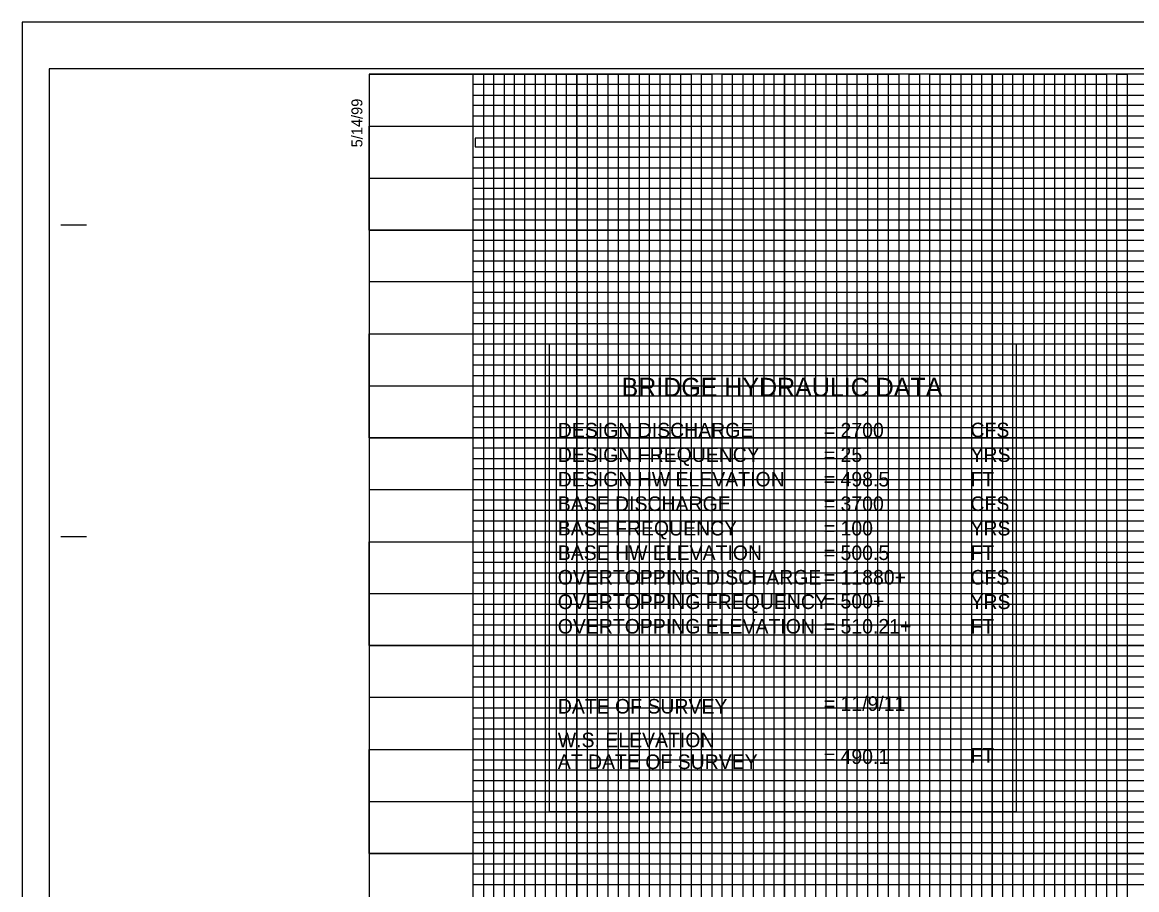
# Model space of a CAD drawing. Extents: x 573715 to 575626, y -55474 to -54374.
# Drawn here: x 573715 to 574252, y -54792 to -54374 of the extents above; entities that cross this region are included whole.
import ezdxf

# ---------------------------------------------------------------- set-up
doc = ezdxf.new("R2010")
doc.units = 0
for name, color, linetype in [('Default', 7, 'Continuous'), ('Prop Grid Mask', 7, 'Continuous'), ('Sheet Cutting Line CELL', 7, 'Continuous'), ('Sheet DOT Grid CELL', 7, 'Continuous'), ('Sheet Layout Profile Border', 7, 'Continuous'), ('Sheet Plot Border Inside CELL', 7, 'Continuous'), ('Sheet Plot Border Outside CELL', 7, 'Continuous'), ('Sheet Profile CELL', 7, 'Continuous'), ('Sheet Profile Grid Major CELL', 7, 'Continuous'), ('Sheet Profile Grid Middle CELL', 7, 'Continuous'), ('Sheet Profile Grid Minor CELL', 7, 'Continuous')]:
    doc.layers.add(name, color=color, linetype=linetype)

msp = doc.modelspace()

# ---------------------------------------------------------------- linework, layer by layer
at = {"layer": 'Prop Grid Mask'}
msp.add_lwpolyline([(573968.92, -54754.28), (574193.92, -54754.28), (574193.92, -54529.28), (573968.92, -54529.28)], close=True, dxfattribs=at)
at = {"layer": 'Sheet Cutting Line CELL'}
for p, q in [((573715.27, -54374.42), (573715.27, -55474.42)), ((575399.27, -54374.42), (573715.27, -54374.42)), ((573715.27, -54374.42), (573715.27, -55474.42))]:
    msp.add_line(p, q, dxfattribs=at)
at = {"layer": 'Sheet DOT Grid CELL'}
for p, q in [((573932.27, -54399.42), (573932.27, -55424.42)), ((573982.27, -54399.42), (573982.27, -55424.42)), ((574032.27, -54399.42), (574032.27, -55424.42)), ((574082.27, -54399.42), (574082.27, -55424.42)), ((574132.27, -54399.42), (574132.27, -55424.42)), ((574182.27, -54399.42), (574182.27, -55424.42)), ((574232.27, -54399.42), (574232.27, -55424.42)), ((573882.27, -54424.42), (575182.22, -54424.42)), ((573882.27, -54474.42), (575182.22, -54474.42)), ((573882.27, -54524.42), (575182.22, -54524.42)), ((573882.27, -54574.42), (575382.27, -54574.42)), ((573882.27, -54624.42), (575382.27, -54624.42)), ((573882.27, -54674.42), (575382.27, -54674.42)), ((573882.27, -54724.42), (575382.27, -54724.42)), ((573882.27, -54774.42), (575382.27, -54774.42))]:
    msp.add_line(p, q, dxfattribs=at)
at = {"layer": 'Sheet Layout Profile Border'}
msp.add_lwpolyline([(573932.27, -54399.42), (573932.27, -55424.42), (575332.27, -55424.42), (575332.27, -54536.97), (575182.22, -54536.97), (575182.22, -54399.42)], close=True, dxfattribs=at)
at = {"layer": 'Sheet Plot Border Inside CELL'}
msp.add_lwpolyline([(575394.77, -54396.87), (573728.27, -54396.87), (573728.27, -55451.97), (575394.77, -55451.97)], close=True, dxfattribs=at)
msp.add_lwpolyline([(575394.77, -54396.87), (573728.27, -54396.87), (573728.27, -55451.97), (575394.77, -55451.97)], close=True, dxfattribs=at)
at = {"layer": 'Sheet Plot Border Outside CELL'}
msp.add_lwpolyline([(575399.27, -54374.42), (573715.27, -54374.42), (573715.27, -55474.42), (575399.27, -55474.42)], close=True, dxfattribs=at)
at = {"layer": 'Sheet Profile CELL'}
for p, q in [((573733.77, -54471.92), (573746.27, -54471.92)), ((573733.77, -54621.92), (573746.27, -54621.92))]:
    msp.add_line(p, q, dxfattribs=at)
msp.add_lwpolyline([(575382.27, -54399.42), (573882.27, -54399.42), (573882.27, -55449.42), (575382.27, -55449.42)], close=True, dxfattribs=at)
at = {"layer": 'Sheet Profile Grid Major CELL'}
for points in [[(573882.27, -54399.42), (573932.27, -54399.42), (573932.27, -55424.42), (573982.27, -55424.42), (573982.27, -54399.42), (574032.27, -54399.42), (574032.27, -55424.42), (574082.27, -55424.42), (574082.27, -54399.42), (574132.27, -54399.42), (574132.27, -55424.42), (574182.27, -55424.42), (574182.27, -54399.42), (574232.27, -54399.42), (574232.27, -55424.42), (574282.27, -55424.42)], [(575182.22, -54474.42), (573882.37, -54474.42), (573882.37, -54424.47), (575182.22, -54424.47)], [(575382.27, -54574.42), (573882.27, -54574.42), (573882.27, -54524.42), (575182.22, -54524.42)], [(575382.27, -54674.42), (573882.27, -54674.42), (573882.27, -54624.42), (575382.27, -54624.42)], [(575382.27, -54774.42), (573882.27, -54774.42), (573882.27, -54724.42), (575382.27, -54724.42)]]:
    msp.add_lwpolyline(points, dxfattribs=at)
at = {"layer": 'Sheet Profile Grid Middle CELL'}
for points in [[(573957.27, -55424.42), (573957.27, -54399.42), (574007.27, -54399.42), (574007.27, -55424.42), (574057.27, -55424.42), (574057.27, -54399.42), (574107.27, -54399.42), (574107.27, -55424.42), (574157.27, -55424.42), (574157.27, -54399.42), (574207.27, -54399.42), (574207.27, -55424.42), (574257.27, -55424.42)], [(573882.27, -54449.42), (575182.22, -54449.42)], [(575182.22, -54499.42), (573882.27, -54499.42), (573882.27, -54549.47), (575382.27, -54549.47)], [(575382.27, -54599.42), (573882.27, -54599.42), (573882.27, -54649.42), (575382.27, -54649.42)], [(575382.27, -54699.42), (573882.27, -54699.42), (573882.27, -54749.42), (575382.27, -54749.42)]]:
    msp.add_lwpolyline(points, dxfattribs=at)
at = {"layer": 'Sheet Profile Grid Minor CELL'}
for p, q in [((575332.27, -54579.42), (573932.27, -54579.42)), ((573932.27, -54579.42), (573932.27, -54584.42)), ((573932.27, -54584.42), (575332.27, -54584.42)), ((575332.27, -54604.42), (573932.27, -54604.42))]:
    msp.add_line(p, q, dxfattribs=at)
for points in [[(573937.27, -54399.42), (573942.27, -54399.42), (573947.27, -54399.42), (573952.27, -54399.42), (573962.27, -54399.42), (573929.22, -54399.42), (573934.22, -54399.42), (573892.27, -54399.42), (573897.27, -54399.42), (573902.27, -54399.42), (573912.27, -54399.42), (573917.27, -54399.42), (573922.27, -54399.42), (573927.27, -54399.42), (573937.27, -54399.42), (573937.27, -55424.42)], [(575182.22, -54404.42), (573932.27, -54404.42), (573932.27, -54409.42), (575182.22, -54409.42)], [(573942.27, -55424.42), (573942.27, -54399.42), (573947.27, -54399.42), (573947.27, -55424.42)], [(573952.27, -55424.42), (573952.27, -54399.42), (573962.27, -54399.42), (573962.27, -55424.42)], [(573967.27, -55424.42), (573967.27, -54399.42), (573972.27, -54399.42), (573972.27, -55424.42)], [(573977.27, -55424.42), (573977.27, -54399.42), (573987.27, -54399.42), (573987.27, -55424.42)], [(573992.27, -55424.42), (573992.27, -54399.42), (573997.27, -54399.42), (573997.27, -55424.42)], [(574002.27, -55424.42), (574002.27, -54399.42), (574012.27, -54399.42), (574012.27, -55424.42)], [(574017.27, -55424.42), (574017.27, -54399.42), (574022.27, -54399.42), (574022.27, -55424.42)], [(574027.27, -55424.42), (574027.27, -54399.42), (574037.27, -54399.42), (574037.27, -55424.42)], [(574042.27, -55424.42), (574042.27, -54399.42), (574047.27, -54399.42), (574047.27, -55424.42)], [(574052.27, -55424.42), (574052.27, -54399.42), (574062.27, -54399.42), (574062.27, -55424.42)], [(574067.27, -55424.42), (574067.27, -54399.42), (574072.27, -54399.42), (574072.27, -55424.42)], [(574077.27, -55424.42), (574077.27, -54399.42), (574087.27, -54399.42), (574087.27, -55424.42)], [(574092.27, -55424.42), (574092.27, -54399.42), (574097.27, -54399.42), (574097.27, -55424.42)], [(574102.27, -55424.42), (574102.27, -54399.42), (574112.27, -54399.42), (574112.27, -55424.42)], [(574117.27, -55424.42), (574117.27, -54399.42), (574122.27, -54399.42), (574122.27, -55424.42)], [(574127.27, -55424.42), (574127.27, -54399.42), (574137.27, -54399.42), (574137.27, -55424.42)], [(574142.27, -55424.42), (574142.27, -54399.42), (574142.27, -54399.42), (574147.27, -54399.42), (574147.27, -55424.42)], [(574152.27, -55424.42), (574152.27, -54399.42), (574162.27, -54399.42), (574162.27, -55424.42)], [(574167.27, -55424.42), (574167.27, -54399.42), (574172.27, -54399.42), (574172.27, -55424.42)], [(574177.27, -55424.42), (574177.27, -54399.42), (574187.27, -54399.42), (574187.27, -55424.42)], [(574192.27, -55424.42), (574192.27, -54399.42), (574197.27, -54399.42), (574197.27, -55424.42)], [(574202.27, -55424.42), (574202.27, -54399.42), (574212.27, -54399.42), (574212.27, -55424.42)], [(574217.27, -55424.42), (574217.27, -54399.42), (574222.27, -54399.42), (574222.27, -55424.42)], [(574227.27, -55424.42), (574227.27, -54399.42), (574237.27, -54399.42), (574237.27, -55424.42)], [(574242.27, -55424.42), (574242.27, -54399.42), (574247.27, -54399.42), (574247.27, -55424.42)], [(575182.22, -54414.42), (573932.27, -54414.42), (573932.27, -54419.42), (575182.22, -54419.42)], [(575182.22, -54430.17), (573933.27, -54430.17), (573933.27, -54434.42), (575182.22, -54434.42)], [(575182.22, -54439.42), (573932.27, -54439.42), (573932.27, -54444.42), (575182.22, -54444.42)], [(575182.22, -54454.42), (573932.27, -54454.42), (573932.27, -54459.42), (575182.22, -54459.42)], [(575182.22, -54464.42), (573932.27, -54464.42), (573932.27, -54469.42), (575182.22, -54469.42)], [(575182.22, -54479.42), (573932.27, -54479.42), (573932.27, -54484.42), (575182.22, -54484.42)], [(575182.22, -54489.42), (573932.27, -54489.42), (573932.27, -54494.42), (575182.22, -54494.42)], [(575182.22, -54504.42), (573932.27, -54504.42), (573932.27, -54509.42), (575182.22, -54509.42)], [(575182.22, -54514.42), (573932.27, -54514.42), (573932.27, -54519.42), (575182.22, -54519.42)], [(575182.22, -54529.42), (573932.27, -54529.42), (573932.27, -54534.42), (575182.22, -54534.42)], [(575332.27, -54539.42), (573932.27, -54539.42), (573932.27, -54539.42), (573932.27, -54559.42), (575332.27, -54559.42)], [(573932.27, -54544.42), (575332.27, -54544.42)], [(575332.27, -54554.42), (573932.27, -54554.42)], [(575332.27, -54564.42), (573932.27, -54564.42), (573932.27, -54569.42), (575332.27, -54569.42)], [(575332.27, -54589.42), (573932.27, -54589.42), (573932.27, -54594.42), (575332.27, -54594.42)], [(575332.27, -54609.42), (573932.27, -54609.42), (573932.27, -54614.42), (575332.27, -54614.42)], [(575332.27, -54619.42), (573932.27, -54619.42)], [(573932.27, -54629.42), (575332.27, -54629.42)], [(575332.27, -54634.42), (573932.27, -54634.42), (573932.27, -54639.42), (575332.27, -54639.42)], [(575332.27, -54644.42), (573932.27, -54644.42), (573932.27, -54654.42), (575332.27, -54654.42)], [(575332.27, -54659.42), (573932.27, -54659.42), (573932.27, -54664.42), (575332.27, -54664.42)], [(575332.27, -54669.42), (573932.27, -54669.42), (573932.27, -54679.42), (575332.27, -54679.42)], [(575332.27, -54684.42), (573932.27, -54684.42), (573932.27, -54689.42), (575332.27, -54689.42)], [(575332.27, -54694.42), (573932.27, -54694.42), (573932.27, -54704.42), (575332.27, -54704.42)], [(575332.27, -54709.42), (573932.27, -54709.42), (573932.27, -54714.42), (575332.27, -54714.42)], [(575332.27, -54719.42), (573932.27, -54719.42), (573932.27, -54729.42), (575332.27, -54729.42)], [(575332.27, -54734.42), (573932.27, -54734.42), (573932.27, -54739.42), (575332.27, -54739.42)], [(575332.27, -54744.42), (573932.27, -54744.42), (573932.27, -54754.42), (575332.27, -54754.42)], [(575332.27, -54759.42), (573932.27, -54759.42), (573932.27, -54764.42), (575332.27, -54764.42)], [(575332.27, -54769.42), (573932.27, -54769.42), (573932.27, -54779.42), (575332.27, -54779.42)], [(575332.27, -54784.42), (573932.27, -54784.42), (573932.27, -54789.42), (575332.27, -54789.42)]]:
    msp.add_lwpolyline(points, dxfattribs=at)

# ---------------------------------------------------------------- texts
at = {"layer": 'Default'}
for s, height, p in [('BRIDGE HYDRAULIC DATA', 9, (574003.82, -54554.53)), ('DESIGN DISCHARGE', 7, (573973.12, -54574.23)), ('= 2700', 7, (574101.19, -54574.23)), ('CFS', 7, (574171.84, -54574.13)), ('DESIGN FREQUENCY', 7, (573973.12, -54586.03)), ('= 25', 7, (574101.19, -54586.03)), ('YRS', 7, (574171.84, -54586.03)), ('DESIGN HW ELEVATION', 7, (573973.12, -54597.83)), ('= 498.5', 7, (574101.19, -54597.83)), ('FT', 7, (574171.84, -54597.83)), ('BASE DISCHARGE', 7, (573973.12, -54609.63)), ('= 3700', 7, (574101.19, -54609.63)), ('CFS', 7, (574171.84, -54609.63)), ('BASE FREQUENCY', 7, (573973.12, -54621.43)), ('= 100', 7, (574101.19, -54621.43)), ('YRS', 7, (574171.84, -54621.43)), ('BASE HW ELEVATION', 7, (573973.12, -54633.23)), ('= 500.5', 7, (574101.19, -54633.23)), ('FT', 7, (574171.84, -54633.23)), ('OVERTOPPING DISCHARGE', 7, (573973.12, -54645.03)), ('= 11880+', 7, (574101.19, -54645.03)), ('CFS', 7, (574171.84, -54645.03)), ('OVERTOPPING FREQUENCY', 7, (573973.12, -54656.83)), ('= 500+', 7, (574101.19, -54656.54)), ('YRS', 7, (574171.84, -54656.83)), ('OVERTOPPING ELEVATION', 7, (573973.12, -54668.63)), ('= 510.21+', 7, (574101.19, -54668.63)), ('FT', 7, (574171.84, -54668.63)), ('= 11/9/11', 7, (574101.19, -54705.83)), ('DATE OF SURVEY', 7, (573973.12, -54707.13)), ('W.S. ELEVATION', 7, (573973.12, -54723.33)), ('AT DATE OF SURVEY', 7, (573973.12, -54733.83)), ('= 490.1', 7, (574101.19, -54731.38)), ('FT', 7, (574171.84, -54730.78))]:
    msp.add_text(s, height=height, dxfattribs=at).set_placement(p)
at = {"layer": 'Sheet Profile CELL'}
msp.add_text('5/14/99', height=5.25, rotation=90, dxfattribs=at).set_placement((573879.02, -54434.62))

doc.saveas('drawing.dxf')
